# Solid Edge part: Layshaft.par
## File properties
Author: Nimesh.N
Template: iso metric part.par
Last saved by: Nimesh.N
Revision: 130
Application: Solid Edge
Density: 7800.000 kg/m^3
Accuracy: 0.990
Username: Nimesh.N
Material: Steel - Free Cutting:1.0764 , 36SMn14
Face Style: Steel
Fill Style: ANSI32(Steel)
Virtual Style: ANSI32(Steel)
Grouping: Steel\Steel - Free Cutting ( Higher P or S content)
LibraryName: Materials-DIN
Coef. of Thermal Exp: 1.1e-05
Thermal Conductivity: 14.0
Specific Heat: 440.0
Modulus of Elasticity: 210000003072.0
Poisson's Ratio: 0.28
Yield Stress: 420000000.0
Ultimate Stress: 670000000.0
Elongation: 0.0
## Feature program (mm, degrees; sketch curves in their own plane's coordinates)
sketch for "unnamed Protrusion 1" plane through (0, 0, 0) normal (0, -1, 0) x-axis (1, 0, 0)
  circle centre (0, 0) radius 34
extrude "unnamed Protrusion 1" add finite 189 along -normal
sketch for "Mid_Bearing" plane through (0, 189, 0) normal (0, 1, 0) x-axis (1, 0, 0)
  circle centre (0, 0) radius 35
extrude "Mid_Bearing" add finite 85 along +normal
sketch for "Gear_B" plane through (0, 274, 0) normal (0, 1, 0) x-axis (0, 0, 1)
  circle centre (0, 0) radius 36
extrude "Gear_B" add finite 165 along +normal
sketch for "Middle_Portion" plane through (0, 439, 0) normal (0, 1, 0) x-axis (0, 0, 1)
  circle centre (0, 0) radius 37
extrude "Middle_Portion" add finite 310 along +normal
sketch for "Gear_C" plane through (0, 749, 0) normal (0, 1, 0) x-axis (0, 0, -1)
  circle centre (0, 0) radius 36
extrude "Gear_C" add finite 150 along +normal
sketch for "Gear_D" plane through (0, 899, 0) normal (0, 1, 0) x-axis (0, 0, -1)
  circle centre (0, 0) radius 35
extrude "Gear_D" add finite 290 along +normal
sketch for "Gear_E" plane through (0, 1189, 0) normal (0, 1, 0) x-axis (0, 0, -1)
  circle centre (0, 0) radius 34
extrude "Gear_E" add finite 188 along +normal
sketch for "Left_Bearing" plane through (0, 0, 0) normal (0, -1, 0) x-axis (1, 0, 0)
  circle centre (0, 0) radius 32.5
extrude "Left_Bearing" add finite 23 along +normal
sketch for "Right_Bearing" plane through (0, 1377, 0) normal (0, 1, 0) x-axis (0, 0, -1)
  circle centre (0, 0) radius 32.5
extrude "Right_Bearing" add finite 23 along +normal
sketch for "unnamed RevolvedCutout 1" #1 plane through (0, 0, 0) normal (1, 0, 0) x-axis (0, 1, 0)
  line (0, 0) -> (0, 0)
  line (0, 0) -> (0, 0)
  line (1032.15, 35) -> (1029.5, 35)
  line (1029.5, 35) -> (1029.5, 33.5)
  line (1029.5, 33.5) -> (1032.15, 33.5)
  line (1032.15, 33.5) -> (1032.15, 35)
sketch for "unnamed RevolvedCutout 1" #2 plane through (0, 0, 0) normal (1, 0, 0) x-axis (0, 1, 0)
  line (1319.5, 34) -> (1319.5, 32.5)
  line (1319.5, 32.5) -> (1322.15, 32.5)
  line (1322.15, 32.5) -> (1322.15, 34)
  line (1322.15, 34) -> (1319.5, 34)
sketch for "unnamed RevolvedCutout 1" #3 plane through (0, 0, 0) normal (1, 0, 0) x-axis (0, 1, 0)
  line (879.5, 34.5) -> (882.15, 34.5)
  line (882.15, 34.5) -> (882.15, 36)
  line (882.15, 36) -> (879.5, 36)
  line (879.5, 36) -> (879.5, 34.5)
sketch for "unnamed RevolvedCutout 1" #4 plane through (0, 0, 0) normal (1, 0, 0) x-axis (0, 1, 0)
  line (305.85, 34.5) -> (308.5, 34.5)
  line (308.5, 34.5) -> (308.5, 36)
  line (308.5, 36) -> (305.85, 36)
  line (305.85, 36) -> (305.85, 34.5)
sketch for "unnamed RevolvedCutout 1" #5 plane through (0, 0, 0) normal (1, 0, 0) x-axis (0, 1, 0)
  line (55.85, 32.5) -> (58.5, 32.5)
  line (58.5, 32.5) -> (58.5, 34)
  line (58.5, 34) -> (55.85, 34)
  line (55.85, 34) -> (55.85, 32.5)
revolve "unnamed RevolvedCutout 1" cut full turn 360 deg about sketch line (0, 0) -> (1377, 0)
sketch for "Keyway_A" plane through (0, 103.5, 0) normal (0, -1, 0) x-axis (-1, 0, 0)
  line (-10.026, -34) -> (10.026, -34)
  line (10.026, -34) -> (10.026, -26.5)
  line (10.026, -26.5) -> (-10.026, -26.5)
  line (-10.026, -26.5) -> (-10.026, -34)
  dimension (linear) = 10.026
  dimension (linear) = 10.026
extrude "Keyway_A" cut finite 40.05 along -normal
sketch for "Keyway_B" plane through (0, 353.5, 0) normal (0, -1, 0) x-axis (1, 0, 0)
  line (-10.025, 28.5) -> (10.025, 28.5)
  line (10.025, 28.5) -> (10.025, 36)
  line (10.025, 36) -> (-10.025, 36)
  line (-10.025, 36) -> (-10.025, 28.5)
  dimension (linear) = 10.025
  dimension (linear) = 10.025
extrude "Keyway_B" cut finite 40.05 along -normal
sketch for "Keyway_C" plane through (0, 834.5, 0) normal (0, 1, 0) x-axis (0, 0, -1)
  line (-36, -10.025) -> (-28.5, -10.025)
  line (-28.5, -10.025) -> (-28.5, 10.025)
  line (-28.5, 10.025) -> (-36, 10.025)
  line (-36, 10.025) -> (-36, -10.025)
  dimension (linear) = 28.5
  dimension (linear) = 28.5
extrude "Keyway_C" cut finite 40.05 along -normal
sketch for "Keyway_D" plane through (0, 984.5, 0) normal (0, 1, 0) x-axis (-1, 0, 0)
  line (-10.025, 27.5) -> (10.025, 27.5)
  line (10.025, 27.5) -> (10.025, 35)
  line (10.025, 35) -> (-10.025, 35)
  line (-10.025, 35) -> (-10.025, 27.5)
  dimension (linear) = 10.025
  dimension (linear) = 10.025
extrude "Keyway_D" cut finite 40.05 along -normal
sketch for "Keyway_E" plane through (0, 1234.5, 0) normal (0, 1, 0) x-axis (-1, 0, 0)
  line (-10.025, 26.5) -> (10.025, 26.5)
  line (10.025, 26.5) -> (10.025, 34)
  line (10.025, 34) -> (-10.025, 34)
  line (-10.025, 34) -> (-10.025, 26.5)
  dimension (linear) = 10.025
  dimension (linear) = 10.025
extrude "Keyway_E" cut finite 40.05 along +normal
chamfer "End_Chamfer" setback 3
fillet "Key_Fillets" radius 10
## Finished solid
Body 1: solid body, 86 faces, 160 edges, 80 vertices.
  Faces by surface: plane 45, cylinder 39, cone 2
  Edges by curve: circle 70, line 70, intersection 20
Bounding box of the edges (mm): 74.000 x 1423.000 x 74.000, from (-37, -23, -37) to (37, 1400, 37).
Cylindrical faces by radius (mm): R10 x20, R32.5 x4, R33.5 x1, R34 x4, R34.5 x2, R35 x3, R36 x4, R37 x1
Conical faces (half-angle, radius in mm at the cone's reference point): 45 deg R32.5 x2
Planar faces by outward normal: +x 5, +y 15, +z 5, -x 5, -y 15
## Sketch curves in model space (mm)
line (0, 0, 0) -> (0, 1377, 0)
line (0, 58.5, 32.5) -> (0, 58.5, 34)
line (0, 58.5, 34) -> (0, 55.85, 34)
line (0, 55.85, 34) -> (0, 55.85, 32.5)
line (0, 55.85, 32.5) -> (0, 58.5, 32.5)
line (0, 308.5, 34.5) -> (0, 308.5, 36)
line (0, 308.5, 36) -> (0, 305.85, 36)
line (0, 305.85, 36) -> (0, 305.85, 34.5)
line (0, 305.85, 34.5) -> (0, 308.5, 34.5)
line (0, 882.15, 34.5) -> (0, 882.15, 36)
line (0, 882.15, 36) -> (0, 879.5, 36)
line (0, 879.5, 36) -> (0, 879.5, 34.5)
line (0, 879.5, 34.5) -> (0, 882.15, 34.5)
line (0, 1032.15, 33.5) -> (0, 1032.15, 35)
line (0, 1032.15, 35) -> (0, 1029.5, 35)
line (0, 1029.5, 35) -> (0, 1029.5, 33.5)
line (0, 1029.5, 33.5) -> (0, 1032.15, 33.5)
line (0, 1322.15, 32.5) -> (0, 1322.15, 34)
line (0, 1322.15, 34) -> (0, 1319.5, 34)
line (0, 1319.5, 34) -> (0, 1319.5, 32.5)
line (0, 1319.5, 32.5) -> (0, 1322.15, 32.5)
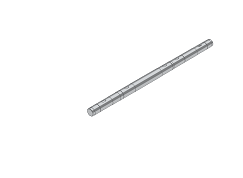
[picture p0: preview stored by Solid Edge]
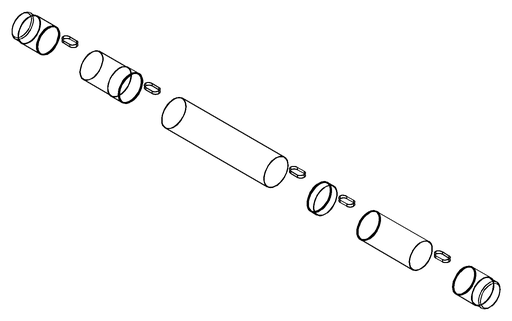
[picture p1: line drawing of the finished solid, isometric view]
